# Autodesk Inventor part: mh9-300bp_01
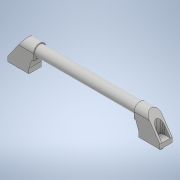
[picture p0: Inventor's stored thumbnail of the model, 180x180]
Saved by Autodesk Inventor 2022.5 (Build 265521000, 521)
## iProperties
Part Number: mh9-300bp_01
Material: 一般
Document SubType Name: Modeling
Designer: ImaoCorp
Density: 1 g/cm^3
Appearance: 既定
Author: ImaoCorp
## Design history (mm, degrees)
feature "mh9-300bp_01"
node "ソリッド1"
